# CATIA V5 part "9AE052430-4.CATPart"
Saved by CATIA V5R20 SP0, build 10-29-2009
Part number: 9AE052430-4
Revision: ANY
Definition: UNKNOWN
Nomenclature: 9AE052430-4
Source: Unknown
Bounding box of the stored display mesh (mm): x -4.935 to 4.935, y -4.756 to 4.756, z -10 to 10
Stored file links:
  C:\Users\Utente\Desktop\IO LAVORO\3D X SITO CF\CUMSA\3D files AE\AE 052430\9AE052430-4.CATPart
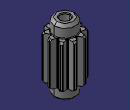
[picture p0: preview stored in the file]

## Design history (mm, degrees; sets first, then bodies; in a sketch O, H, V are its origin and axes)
Body1 "Cortar-Revolución1" (main body)
  Solid1: solid without history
